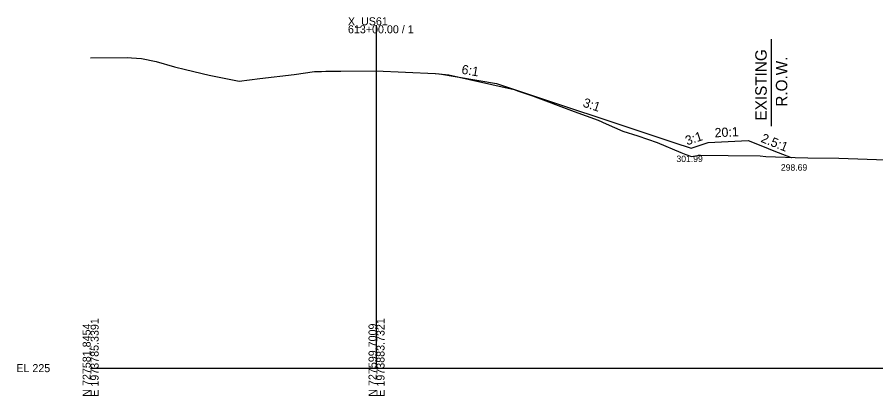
# Model space of a CAD drawing. Extents: x -26 to 1604, y -13 to 9623.
# Drawn here: x -25.7 to 274.6, y 2490.3 to 2622.8 of the extents above; entities that cross this region are included whole.
import ezdxf

# ---------------------------------------------------------------- set-up
doc = ezdxf.new("R2010")
doc.units = 0
for name, color, linetype in [('Draft_XS_Grid', 7, 'Continuous'), ('DTM_X_GROUND', 7, 'Continuous'), ('SLOPE_STAKES_FILL', 7, 'Continuous'), ('XS_CELL', 7, 'Continuous'), ('XS_P_GROUND', 7, 'Continuous'), ('XS_P_TX_DCH', 7, 'Continuous'), ('XS_P_TX_FS_BS', 7, 'Continuous'), ('XS_X_ROW', 7, 'Continuous')]:
    doc.layers.add(name, color=color, linetype=linetype)

msp = doc.modelspace()

# ---------------------------------------------------------------- linework, layer by layer
at = {"layer": 'DTM_X_GROUND'}
msp.add_lwpolyline([(0, 2608.66), (12.89, 2608.75), (14.3, 2608.62), (17.77, 2608.32), (22.95, 2607.27), (29.29, 2605.45), (33.18, 2604.48), (41.44, 2602.57), (52, 2600.45), (59.17, 2601.32), (71.24, 2602.79), (78.25, 2603.77), (80.78, 2603.87), (82.22, 2603.92), (87.47, 2603.96), (99.72, 2604.03), (120.48, 2603.12), (120.56, 2603.12), (120.6, 2603.11), (125.3, 2602.69), (132.55, 2601.07), (148.15, 2597.5), (149.7, 2596.91), (154.6, 2595.32), (169.15, 2589.87), (177.53, 2586.78), (180.27, 2585.56), (186.2, 2582.97), (191.38, 2581.25), (198.13, 2579.01), (206.48, 2575.53), (207.59, 2575), (208.17, 2574.79), (210.19, 2574.05), (212.34, 2574.48), (212.66, 2574.54), (213.27, 2574.53), (222.99, 2574.47), (234.18, 2574.33), (236.19, 2574.1), (239.57, 2573.99), (246.47, 2573.69), (250.83, 2573.65), (261.66, 2573.47), (281.47, 2572.75)], dxfattribs=at)
at = {"layer": 'XS_CELL'}
for p, q in [((100, 2500), (100, 2620)), ((0, 2500), (100, 2500)), ((100, 2500), (600, 2500))]:
    msp.add_line(p, q, dxfattribs=at)
at = {"layer": 'XS_P_GROUND'}
for points in [[(122, 2602.99), (142, 2599.65)], [(142, 2599.65), (204, 2578.99), (210, 2576.99), (216, 2578.99), (230, 2579.69), (235, 2577.69)], [(235, 2577.69), (239, 2576.09), (245, 2573.69)], [(245, 2573.69), (245.15, 2573.75)]]:
    msp.add_lwpolyline(points, dxfattribs=at)
at = {"layer": 'XS_X_ROW'}
msp.add_line((238, 2615.19), (238, 2584.65), dxfattribs=at)

# ---------------------------------------------------------------- texts
at = {"layer": 'Draft_XS_Grid'}
msp.add_text('-', height=0.0001, dxfattribs=at).set_placement((0, 2500))
at = {"layer": 'SLOPE_STAKES_FILL'}
for p in [(141.96, 2599.59), (203.96, 2578.93), (209.96, 2576.93), (215.96, 2578.93), (229.96, 2579.63), (238.96, 2576.03), (244.96, 2573.63), (245.11, 2573.69)]:
    msp.add_text('X', height=0.12, dxfattribs=at).set_placement(p)
at = {"layer": 'XS_CELL'}
for s, p in [('X_US61', (90, 2620)), ('613+00.00 / 1', (90, 2617.2)), ('EL 225', (-26, 2498.6))]:
    msp.add_text(s, height=2.8, dxfattribs=at).set_placement(p)
for s, p in [('E 1973785.3391', (2.8, 2490)), ('E 1973883.7321', (102.8, 2490)), ('N 727581.8454', (0, 2490)), ('N 727599.7009', (100, 2490))]:
    msp.add_text(s, height=2.8, rotation=90, dxfattribs=at).set_placement(p)
at = {"layer": 'XS_P_GROUND'}
for p in [(121.96, 2602.93), (234.96, 2577.63)]:
    msp.add_text('X', height=0.12, dxfattribs=at).set_placement(p)
at = {"layer": 'XS_P_TX_DCH'}
for s, p in [('301.99', (204.91, 2572.15)), ('298.69', (241.44, 2569.12))]:
    msp.add_text(s, height=2.25, dxfattribs=at).set_placement(p)
at = {"layer": 'XS_P_TX_FS_BS'}
for s, rotation, p in [('6:1', 350.5377, (129.56, 2603.06)), ('3:1', 341.5651, (171.93, 2591.59)), ('20:1', 2.8624, (218.33, 2580.77)), ('3:1', 18.4349, (208.62, 2577.96)), ('2.5:1', 338.1986, (234.19, 2579.26))]:
    msp.add_text(s, height=3.24, rotation=rotation, dxfattribs=at).set_placement(p)
at = {"layer": 'XS_X_ROW'}
for s, p in [('EXISTING', (236.48, 2586.66)), ('R.O.W.', (243.68, 2591.51))]:
    msp.add_text(s, height=4, rotation=90, dxfattribs=at).set_placement(p)

doc.saveas('drawing.dxf')
